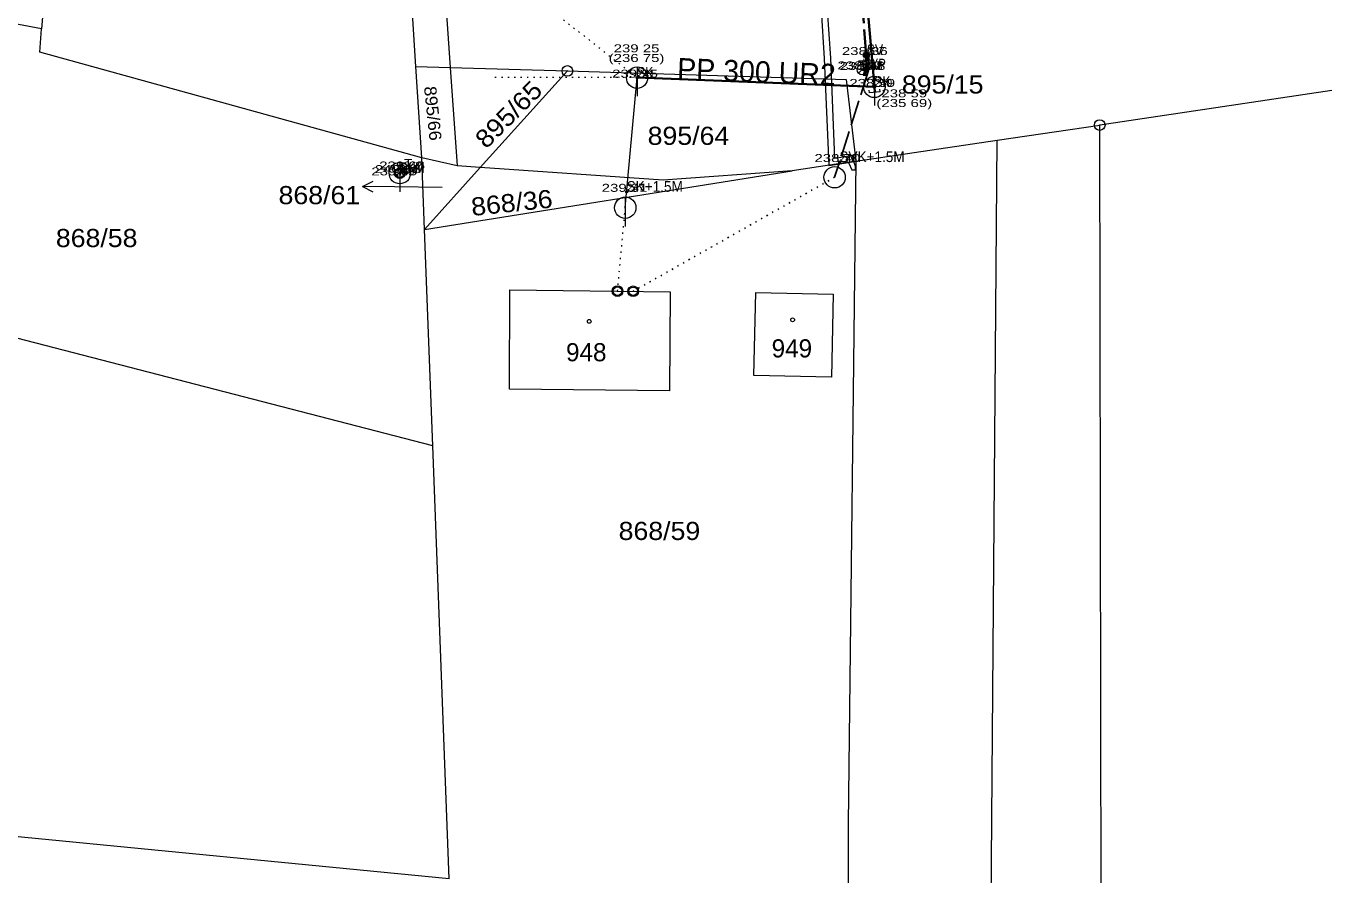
# Model space of a CAD drawing. Extents: x -686207 to -681951, y -1020493 to -1017811.
# Drawn here: x -682433.3 to -682310.9, y -1019257.8 to -1019178.2 of the extents above; entities that cross this region are included whole.
import ezdxf
from ezdxf.enums import TextEntityAlignment as Align

# ---------------------------------------------------------------- set-up
doc = ezdxf.new("R2010")
doc.units = 0
doc.header["$LTSCALE"] = 0.4
doc.header["$PDMODE"] = 32
doc.header["$PDSIZE"] = 0.2
doc.linetypes.add('DOTTED', pattern=[1.5, 0.3, -1.2])
doc.linetypes.add('LONG_DASHED', pattern=[7.5, 6, -1.5])
for name, color, linetype, lineweight in [('1', 7, 'Continuous', 13), ('10', 7, 'Continuous', 13), ('12', 7, 'Continuous', 13), ('13', 7, 'Continuous', 13), ('3', 7, 'Continuous', 13), ('35', 7, 'LONG_DASHED', 35), ('4', 7, 'Continuous', 13), ('45', 7, 'Continuous', 35), ('5', 7, 'Continuous', 13), ('50', 7, 'LONG_DASHED', 25), ('51', 7, 'DOTTED', 25), ('7', 7, 'Continuous', 13), ('8', 7, 'Continuous', 13)]:
    doc.layers.add(name, color=color, linetype=linetype, lineweight=lineweight)
for name, color, linetype in [('15', 7, 'Continuous'), ('2', 7, 'Continuous'), ('20', 7, 'Continuous')]:
    doc.layers.add(name, color=color, linetype=linetype)

msp = doc.modelspace()

# ---------------------------------------------------------------- linework, layer by layer
at = {"layer": '1'}
for p, q in [((-682396.74, -1019182.01), (-682399.46, -1019139.81)), ((-682396.74, -1019182.01), (-682393.51, -1019182.11)), ((-682396.19, -1019190.58), (-682396.74, -1019182.01)), ((-682393.51, -1019182.11), (-682392.86, -1019191.34)), ((-682393.51, -1019182.11), (-682382.54, -1019182.44)), ((-682382.54, -1019182.44), (-682390.7, -1019191.49)), ((-682382.54, -1019182.44), (-682356.4, -1019183.25)), ((-682356.4, -1019183.25), (-682355.51, -1019190.91)), ((-682310.89, -1019184.26), (-682332.65, -1019187.51)), ((-682342.27, -1019188.94), (-682332.65, -1019187.51)), ((-682332.49, -1019265.58), (-682332.65, -1019187.51)), ((-682355.51, -1019190.91), (-682342.27, -1019188.94)), ((-682344.2, -1019433.04), (-682342.27, -1019188.94)), ((-682392.86, -1019191.34), (-682396.19, -1019190.58)), ((-682395.93, -1019197.29), (-682396.19, -1019190.58)), ((-682355.51, -1019190.91), (-682361.47, -1019191.8)), ((-682355.51, -1019190.91), (-682356.23, -1019253)), ((-682390.7, -1019191.49), (-682395.93, -1019197.29)), ((-682395.93, -1019197.29), (-682361.47, -1019191.8)), ((-682390.7, -1019191.49), (-682392.86, -1019191.34)), ((-682395.16, -1019217.56), (-682395.93, -1019197.29)), ((-682395.16, -1019217.56), (-682462.35, -1019200.2)), ((-682393.61, -1019258.15), (-682395.16, -1019217.56)), ((-682393.61, -1019258.15), (-682544.83, -1019243.4)), ((-682356.23, -1019253), (-682356.23, -1019268.14))]:
    msp.add_line(p, q, dxfattribs=at)
for points in [[(-682428.26, -1019136.43), (-682431.81, -1019178.49), (-682451.08, -1019174.85)], [(-682359.41, -1019176.7), (-682393.95, -1019175.76), (-682393.51, -1019182.11)], [(-682396.19, -1019190.58), (-682431.97, -1019180.69), (-682431.81, -1019178.49)], [(-682361.47, -1019191.8), (-682373.56, -1019192.68), (-682390.7, -1019191.49)]]:
    msp.add_lwpolyline(points, dxfattribs=at)
for points in [[(-682372.97, -1019212.42), (-682387.95, -1019212.26), (-682387.93, -1019202.96), (-682372.89, -1019203.13)], [(-682357.78, -1019211.14), (-682365.05, -1019210.97), (-682364.88, -1019203.2), (-682357.62, -1019203.37)]]:
    msp.add_lwpolyline(points, close=True, dxfattribs=at)
for p in [(-682354.47, -1019180.95), (-682354.89, -1019182.3), (-682354.68, -1019182.35), (-682376, -1019183.07), (-682353.77, -1019183.94), (-682357.04, -1019190.98), (-682398.57, -1019192.23), (-682398.24, -1019192.02), (-682397.83, -1019191.68), (-682376.98, -1019193.77)]:
    msp.add_point(p, dxfattribs=at)
at = {"layer": '10'}
for p, q in [((-682376, -1019182.07), (-682376, -1019184.818)), ((-682355.244, -1019182.654), (-682354.537, -1019181.947)), ((-682355.24, -1019181.5), (-682354.54, -1019181.5)), ((-682354.89, -1019181.8), (-682354.89, -1019181.5)), ((-682353.77, -1019182.94), (-682353.77, -1019185.688)), ((-682354.225, -1019184.481), (-682354.247, -1019184.232)), ((-682353.229, -1019184.395), (-682354.225, -1019184.481)), ((-682353.229, -1019184.395), (-682353.25, -1019184.146)), ((-682398.24, -1019191.02), (-682398.24, -1019193.768)), ((-682377.117, -1019194.264), (-682377.117, -1019197.012))]:
    msp.add_line(p, q, dxfattribs=at)
for points in [[(-682354.32, -1019181.45), (-682354.62, -1019180.45), (-682354.32, -1019180.45), (-682354.62, -1019181.45)], [(-682354.53, -1019182.85), (-682354.83, -1019181.85), (-682354.53, -1019181.85), (-682354.83, -1019182.85)]]:
    msp.add_lwpolyline(points, close=True, dxfattribs=at)
for centre, radius in [((-682376, -1019183.071), 1.0002), ((-682354.889, -1019182.3), 0.5), ((-682353.77, -1019183.941), 1.0002), ((-682398.24, -1019192.021), 1.0002), ((-682357.492, -1019192.41), 1), ((-682377.117, -1019195.265), 1.0002)]:
    msp.add_circle(centre, radius, dxfattribs=at)
at = {"layer": '12'}
for centre, radius in [((-682354.52, -1019180.946), 0.3), ((-682354.52, -1019180.946), 0.2), ((-682354.52, -1019180.946), 0.1), ((-682354.47, -1019182.4), 0.15), ((-682354.47, -1019182.4), 0.075), ((-682398.24, -1019192.02), 0.5), ((-682398.24, -1019192.02), 0.4), ((-682377.832, -1019203.074), 0.5), ((-682377.832, -1019203.074), 0.4), ((-682376.369, -1019203.091), 0.5), ((-682376.369, -1019203.091), 0.4)]:
    msp.add_circle(centre, radius, dxfattribs=at)
at = {"layer": '13'}
for points in [[(-682360.15, -1019157.1), (-682359.41, -1019166.94), (-682358.76, -1019176.72), (-682358.46, -1019181.28), (-682358.04, -1019191.29), (-682356.2, -1019191.01), (-682355.68, -1019190.93), (-682355.83, -1019190.36), (-682357.46, -1019190.65), (-682357.86, -1019181.24), (-682358.16, -1019176.73), (-682358.81, -1019166.9), (-682359.55, -1019157.06), (-682359.68, -1019152.4), (-682359.77, -1019150.14), (-682360.76, -1019150.15), (-682360.77, -1019149.73), (-682361.04, -1019149.78), (-682361.01, -1019151.14), (-682360.71, -1019151.12), (-682360.72, -1019150.75), (-682360.35, -1019150.74), (-682360.28, -1019152.42)], [(-682355.89, -1019191.72), (-682355.55, -1019191.72), (-682355.55, -1019191.4), (-682355.68, -1019190.93), (-682356.2, -1019191.01)]]:
    msp.add_lwpolyline(points, close=True, dxfattribs=at)
at = {"layer": '35'}
for p, q in [((-682354.52, -1019180.946), (-682356.39, -1019157.641)), ((-682354.47, -1019182.4), (-682354.52, -1019180.946)), ((-682354.89, -1019182.3), (-682354.68, -1019182.35)), ((-682354.68, -1019182.35), (-682354.47, -1019182.4))]:
    msp.add_line(p, q, dxfattribs=at)
at = {"layer": '45'}
for p, q in [((-682353.77, -1019183.94), (-682355.484, -1019163.871)), ((-682376, -1019183.07), (-682353.77, -1019183.94)), ((-682353.727, -1019184.438), (-682353.77, -1019183.94))]:
    msp.add_line(p, q, dxfattribs=at)
at = {"layer": '5'}
for centre in [(-682380.4868, -1019205.9092), (-682361.4268, -1019205.7692)]:
    msp.add_circle(centre, 0.175, dxfattribs=at)
at = {"layer": '50'}
msp.add_line((-682354.52, -1019180.946), (-682354.47, -1019180.95), dxfattribs=at)
at = {"layer": '50', "linetype": 'Continuous', "lineweight": 13}
msp.add_line((-682377.117, -1019195.264), (-682376, -1019183.07), dxfattribs=at)
at = {"layer": '50'}
msp.add_lwpolyline([(-682354.47, -1019180.95), (-682354.279, -1019180.964), (-682354.325, -1019182.385), (-682357.04, -1019190.98), (-682357.492, -1019192.41)], dxfattribs=at)
at = {"layer": '51', "lineweight": 13}
for p, q in [((-682383.839, -1019176.904), (-682376, -1019183.07)), ((-682376, -1019183.07), (-682389.354, -1019183.047)), ((-682377.832, -1019203.074), (-682377.117, -1019195.264))]:
    msp.add_line(p, q, dxfattribs=at)
at = {"layer": '51'}
msp.add_line((-682357.492, -1019192.41), (-682376.369, -1019203.091), dxfattribs=at)
at = {"layer": '7'}
for p, q in [((-682401.751, -1019193.258), (-682400.758, -1019193.776)), ((-682394.26, -1019193.36), (-682398.75, -1019193.31))]:
    msp.add_line(p, q, dxfattribs=at)
msp.add_lwpolyline([(-682398.75, -1019193.31), (-682401.751, -1019193.258), (-682400.74, -1019192.774)], dxfattribs=at)
at = {"layer": '8'}
for centre, radius in [((-682382.54, -1019182.4399), 0.5), ((-682382.54, -1019182.4399), 0.0303), ((-682332.65, -1019187.5099), 0.5), ((-682332.65, -1019187.5099), 0.0303)]:
    msp.add_circle(centre, radius, dxfattribs=at)

# ---------------------------------------------------------------- texts
at = {"layer": '15'}
msp.add_text('PP 300 UR2', height=2, rotation=357.759, dxfattribs=at).set_placement((-682364.8541, -1019183.5063), align=Align.CENTER)
at = {"layer": '2'}
for s, height, p in [('237', 0.75, (-682354.47, -1019180.95)), ('241', 0.75, (-682376, -1019183.07)), ('239', 0.75, (-682354.89, -1019182.3)), ('238', 0.75, (-682354.68, -1019182.35)), ('240', 0.75, (-682353.77, -1019183.94)), ('242', 0.75, (-682397.83, -1019191.68)), ('248', 0.75, (-682357.04, -1019190.98)), ('243', 0.75, (-682398.57, -1019192.23)), ('244', 0.75, (-682398.24, -1019192.02)), ('247', 0.75, (-682376.98, -1019193.77)), ('948', 1.7, (-682382.664, -1019209.65)), ('949', 1.7, (-682363.394, -1019209.289))]:
    msp.add_text(s, height=height, dxfattribs=at).set_placement(p)
at = {"layer": '2', "width": 1.1}
for s, height, rotation, p in [('895/65', 1.7, 45, (-682390.146, -1019189.818)), ('895/66', 1.139, 276, (-682395.977, -1019183.926)), ('868/36', 1.7, 6, (-682391.461, -1019196.035))]:
    msp.add_text(s, height=height, rotation=rotation, dxfattribs=at).set_placement(p)
for s, p in [('895/15', (-682351.19, -1019184.559)), ('895/64', (-682375.015, -1019189.37)), ('868/61', (-682409.605, -1019194.929)), ('868/58', (-682430.475, -1019198.95)), ('868/59', (-682377.735, -1019226.4))]:
    msp.add_text(s, height=1.7, dxfattribs=at).set_placement(p)
at = {"layer": '20', "width": 1.4}
for s, p in [('239 25 ', (-682375.86, -1019180.697)), ('(236 75) ', (-682375.86, -1019181.604)), ('238 59 ', (-682350.769, -1019184.917)), ('(235 69) ', (-682350.768, -1019185.825))]:
    msp.add_text(s, height=0.75, dxfattribs=at).set_placement(p, align=Align.CENTER)
at = {"layer": '3', "width": 1.4}
for s, p in [('238 36 ', (-682354.47, -1019180.95)), ('239 25 ', (-682376, -1019183.07)), ('238 47 ', (-682354.89, -1019182.3)), ('238 48 ', (-682354.68, -1019182.35)), ('238 59 ', (-682353.77, -1019183.94)), ('239 66 ', (-682397.83, -1019191.68)), ('238 70 ', (-682357.04, -1019190.98)), ('239 66 ', (-682398.57, -1019192.23)), ('240 38 ', (-682398.24, -1019192.02)), ('239 31 ', (-682376.98, -1019193.77))]:
    msp.add_text(s, height=0.75, dxfattribs=at).set_placement(p, align=Align.CENTER)
at = {"layer": '4'}
for s, width, p in [('SV', 0.85, (-682354.47, -1019180.95)), ('SK', 0.85, (-682376, -1019183.07)), ('HYP', 0.8, (-682354.89, -1019182.3)), ('SV', 0.85, (-682354.68, -1019182.35)), ('SK', 0.85, (-682353.77, -1019183.94)), ('SKM', 0.8, (-682398.24, -1019192.02)), ('T', 0.95, (-682397.83, -1019191.68)), ('SVK+1.5M', 0.95, (-682357.04, -1019190.98)), ('T', 0.95, (-682398.57, -1019192.23)), ('SK+1.5M', 0.95, (-682376.98, -1019193.77))]:
    msp.add_text(s, height=1, dxfattribs=dict(at, width=width)).set_placement(p)

doc.saveas('drawing.dxf')
